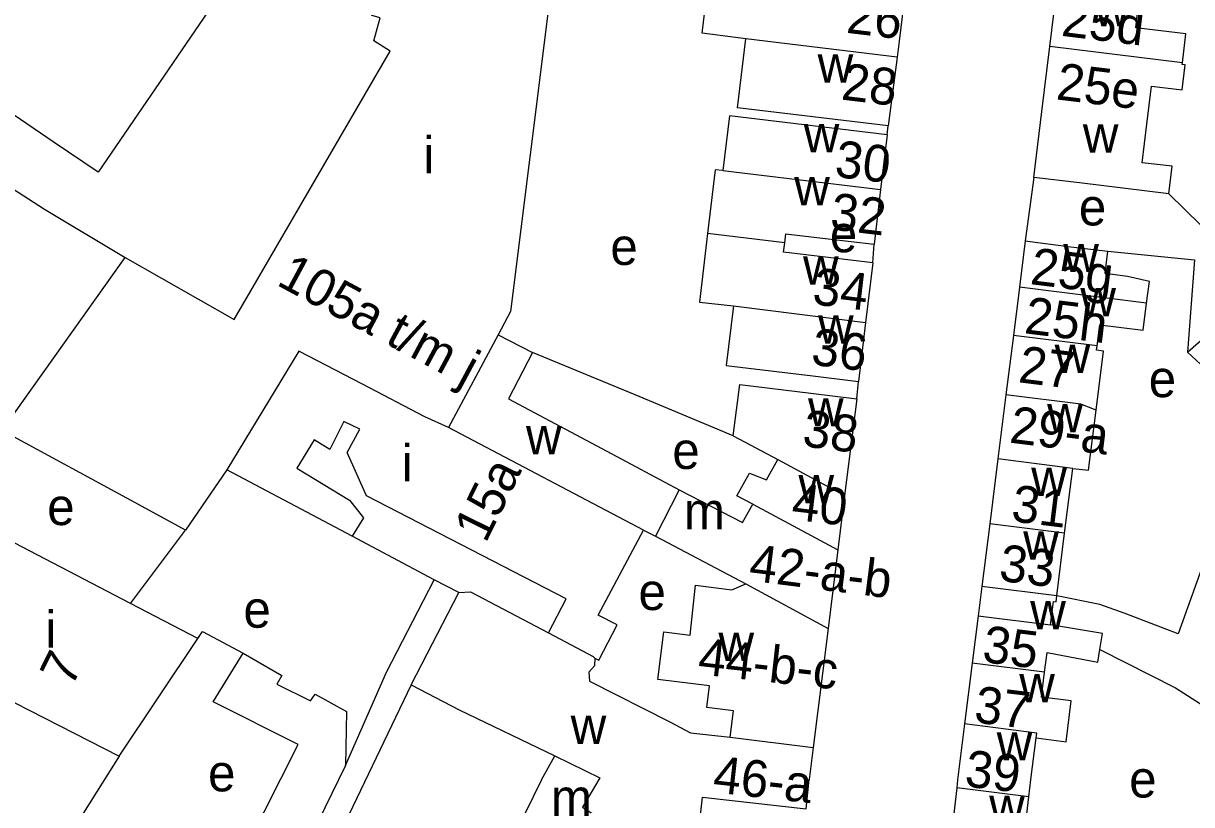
# Model space of a CAD drawing. Extents: x 159700 to 161346, y 381730 to 382922.
# Drawn here: x 160801.9 to 160928.7, y 382497.3 to 382582.1 of the extents above; entities that cross this region are included whole.
import ezdxf

# ---------------------------------------------------------------- set-up
doc = ezdxf.new("R2010")
doc.units = 0
for name, color, linetype in [('BLT_Basislijn', 7, 'Continuous'), ('BLT_Bebouwing', 7, 'Continuous'), ('BLT_Centroide', 7, 'Continuous'), ('BLT_Huisnummer', 7, 'Continuous'), ('BLT_Huisnummer_ tussenligend', 7, 'Continuous'), ('BLT_Huisnummer_reeks', 7, 'Continuous'), ('BLT_Onderdoorgang_en_onderverdeling', 7, 'Continuous'), ('BLT_Onderverdeling_panden', 7, 'Continuous')]:
    doc.layers.add(name, color=color, linetype=linetype)

msp = doc.modelspace()

# ---------------------------------------------------------------- linework, layer by layer
at = {"layer": 'BLT_Basislijn'}
for p, q in [((160895.67, 382570.01), (160895.79, 382570.98)), ((160797.58, 382566.19), (160804.24, 382561.93)), ((160911.6, 382565.37), (160910.65, 382558.47)), ((160804.24, 382561.93), (160813, 382556.68)), ((160894.11, 382556.11), (160894.25, 382558.11)), ((160868.34, 382541.79), (160857.19, 382546.37)), ((160892.39, 382541.35), (160892.57, 382543.22)), ((160878.98, 382537.32), (160868.34, 382541.79)), ((160813.56, 382519.14), (160819.53, 382527.09)), ((160846.52, 382521.7), (160837.63, 382526.42)), ((160841.34, 382511.67), (160846.52, 382521.7)), ((160849.19, 382520.32), (160846.52, 382521.7)), ((160836.89, 382501.55), (160841.34, 382511.67)), ((160844.01, 382510.3), (160831.41, 382483.99)), ((160812.33, 382502.56), (160805.67, 382492.01))]:
    msp.add_line(p, q, dxfattribs=at)
for points in [[(160951.83, 382567.37), (160949.25, 382570.37), (160948.92, 382570.37), (160946.35, 382568.47), (160933.21, 382556.75), (160926.24, 382563.59)], [(160919.62, 382557.35), (160929.02, 382556.44), (160928.26, 382546.4)], [(160934.87, 382533.23), (160932.92, 382532.91), (160931.78, 382529.63), (160932.15, 382529.42), (160927.26, 382515.85), (160921.38, 382518.08)], [(160921.38, 382518.08), (160918.77, 382519.01), (160914.08, 382519.95)], [(160820.88, 382515.32), (160821.39, 382516.08), (160825.78, 382513.72)], [(160918.77, 382514.15), (160926.98, 382509.98), (160933.19, 382505.98), (160932.52, 382501.95)]]:
    msp.add_lwpolyline(points, dxfattribs=at)
at = {"layer": 'BLT_Bebouwing'}
for p, q in [((160860.97, 382600.04), (160854.79, 382550.82)), ((160913.33, 382579.57), (160914.11, 382585.95)), ((160912.47, 382572.52), (160913.33, 382579.57)), ((160896.76, 382578.41), (160895.79, 382570.98)), ((160911.6, 382565.37), (160912.47, 382572.52)), ((160895.67, 382570.01), (160894.96, 382564.07)), ((160894.96, 382564.07), (160894.25, 382558.11)), ((160910.65, 382558.47), (160910.03, 382553.46)), ((160928.26, 382546.4), (160940.68, 382557.44)), ((160894.11, 382556.11), (160893.34, 382549.63)), ((160910.03, 382553.46), (160909.37, 382548.22)), ((160854.79, 382550.82), (160853.45, 382548.3)), ((160893.34, 382549.63), (160892.57, 382543.22)), ((160853.45, 382548.3), (160857.19, 382546.37)), ((160909.37, 382548.22), (160908.56, 382541.77)), ((160857.19, 382546.37), (160854.59, 382541.34)), ((160936.84, 382538.5), (160928.26, 382546.4)), ((160854.59, 382541.34), (160865.24, 382535.67)), ((160892.39, 382541.35), (160891.04, 382530.84)), ((160908.56, 382541.77), (160907.69, 382534.81)), ((160878.98, 382537.32), (160883.83, 382534.74)), ((160865.24, 382535.67), (160873.12, 382531.47)), ((160907.69, 382534.81), (160906.81, 382527.79)), ((160824.03, 382533.65), (160819.53, 382527.09)), ((160837.63, 382526.42), (160824.03, 382533.65)), ((160914.93, 382526.77), (160915.81, 382533.79)), ((160873.12, 382531.47), (160879.98, 382527.92)), ((160891.04, 382530.84), (160890.34, 382524.96)), ((160819.53, 382527.09), (160814.42, 382529.87)), ((160879.98, 382527.92), (160881.1, 382529.9)), ((160869.25, 382527.1), (160870.52, 382526.43)), ((160906.81, 382527.79), (160905.95, 382520.97)), ((160870.52, 382526.43), (160880.33, 382521.26)), ((160890.34, 382524.96), (160889.27, 382516.43)), ((160905.95, 382520.97), (160905.55, 382517.79)), ((160905.55, 382517.79), (160904.91, 382512.65)), ((160889.27, 382516.43), (160888.66, 382511.52)), ((160888.66, 382511.52), (160887.66, 382503.5)), ((160904.91, 382512.65), (160904.08, 382506.05)), ((160904.08, 382506.05), (160903.32, 382500)), ((160911.28, 382500.02), (160911.85, 382504.53)), ((160858.17, 382500), (160859.63, 382502.61)), ((160887.66, 382503.5), (160887.22, 382500.01)), ((160858.17, 382500), (160854.89, 382493.28)), ((160886.88, 382496.85), (160887.22, 382500.01)), ((160903.32, 382500), (160903.22, 382499.11)), ((160911.05, 382498.13), (160911.28, 382500.02)), ((160903.22, 382499.11), (160902.35, 382491.51)), ((160910.19, 382490.61), (160911.05, 382498.13))]:
    msp.add_line(p, q, dxfattribs=at)
for points in [[(160841.73, 382579.06), (160839.99, 382580.2), (160840.67, 382582.69), (160839.76, 382582.95), (160849.45, 382602.5), (160857.43, 382600.35), (160860.02, 382604.55)], [(160835.82, 382601.89), (160833.5, 382598.49), (160833.58, 382598.43), (160831.95, 382596.05), (160831.04, 382596.67), (160810.06, 382565.93), (160805.18, 382569.24), (160794.52, 382576.51)], [(160880.34, 382580.41), (160875.6, 382581.03), (160876.05, 382584.63), (160885.71, 382583.41), (160886.18, 382587.2)], [(160897.67, 382585.83), (160896.99, 382580.17), (160896.76, 382578.41)], [(160927.71, 382577.82), (160928.09, 382580.94), (160922.65, 382581.61), (160923.04, 382584.86)], [(160895.79, 382570.98), (160879.45, 382572.93), (160880.34, 382580.41)], [(160813, 382556.68), (160824.82, 382549.96), (160841.73, 382579.06)], [(160923.86, 382571.15), (160924.36, 382575.29), (160927.69, 382574.88), (160928.02, 382577.6), (160927.69, 382577.64), (160927.71, 382577.82)], [(160895.67, 382570.01), (160878.55, 382572.06), (160877.84, 382566.11)], [(160926.24, 382563.59), (160926.61, 382566.58), (160923.35, 382566.97), (160923.86, 382571.15)], [(160877.84, 382566.11), (160877.02, 382566.21), (160876.19, 382559.27)], [(160926.24, 382563.59), (160916.56, 382564.77), (160911.6, 382565.37)], [(160876.19, 382559.27), (160875.3, 382551.82), (160878.99, 382551.44)], [(160884.56, 382558.27), (160884.68, 382559.26), (160889.29, 382558.71), (160894.25, 382558.11)], [(160910.65, 382558.47), (160915.62, 382557.85), (160919.62, 382557.35)], [(160894.11, 382556.11), (160884.44, 382557.27), (160884.56, 382558.27)], [(160923.83, 382551.73), (160924.13, 382554.09), (160921.75, 382554.62), (160919.32, 382554.93), (160919.62, 382557.35)], [(160799.64, 382537.89), (160813, 382556.68)], [(160878.99, 382551.44), (160878.2, 382544.94), (160887.6, 382543.82), (160892.57, 382543.22)], [(160918.45, 382547.08), (160918.74, 382549.38), (160923.46, 382548.78), (160923.83, 382551.73)], [(160918.34, 382540.12), (160919.15, 382546.53), (160918.39, 382546.62), (160918.45, 382547.08)], [(160878.98, 382537.32), (160879.68, 382542.88), (160887.38, 382541.96), (160892.39, 382541.35)], [(160915.81, 382533.79), (160917.52, 382533.58), (160918.34, 382540.12)], [(160858.93, 382515.93), (160860.86, 382519.63), (160839.16, 382530.8), (160837.07, 382535.5), (160838.44, 382538.05), (160836.73, 382538.89), (160835.2, 382535.85), (160833.49, 382536.88), (160831.62, 382533.8), (160837.32, 382530.35), (160838.85, 382528.42), (160837.63, 382526.42)], [(160814.42, 382529.87), (160799.64, 382537.89)], [(160881.1, 382529.9), (160879.36, 382530.83), (160880.75, 382533.29), (160882.59, 382532.55), (160883.83, 382534.74)], [(160813.56, 382519.14), (160798.42, 382527.03), (160799.16, 382528.46)], [(160863.94, 382513.21), (160864.39, 382512.97), (160866.37, 382516.8), (160864.32, 382517.85), (160869.25, 382527.1)], [(160914.08, 382519.95), (160914.93, 382526.77)], [(160795.05, 382520.98), (160791.22, 382513.34), (160812.33, 382502.56)], [(160844.01, 382510.3), (160849.19, 382520.32)], [(160849.19, 382520.32), (160850.45, 382520.39), (160858.93, 382515.93)], [(160878.65, 382504.63), (160879.01, 382507.46), (160876.1, 382507.83), (160876.4, 382510.18), (160870.79, 382510.89), (160871.44, 382516.04), (160874.29, 382515.68), (160874.88, 382521.11), (160878.83, 382520.61), (160880.33, 382521.26)], [(160820.88, 382515.32), (160813.56, 382519.14)], [(160913.4, 382516.82), (160913.71, 382519.35), (160914, 382519.31), (160914.08, 382519.95)], [(160918.77, 382514.15), (160919.06, 382515.87), (160913.4, 382516.82)], [(160812.33, 382502.56), (160820.88, 382515.32)], [(160912.74, 382511.67), (160913.03, 382513.82), (160918.54, 382512.75), (160918.77, 382514.15)], [(160824.37, 382489.21), (160831.76, 382503.82), (160822.54, 382508.46), (160825.78, 382513.72)], [(160825.78, 382513.72), (160830, 382511.33), (160829.45, 382510.38), (160833.1, 382508.56), (160833.61, 382509.3), (160837, 382507.39)], [(160863.94, 382513.21), (160863.91, 382512.36), (160863.3, 382511.66), (160863.37, 382510.71), (160872.1, 382506.28), (160874.32, 382505.08), (160878.65, 382504.63)], [(160911.85, 382504.53), (160915.11, 382504.13), (160915.65, 382508.56), (160912.43, 382508.96), (160912.74, 382511.67)], [(160844.01, 382510.3), (160849.22, 382507.57), (160859.63, 382502.61)], [(160837, 382507.39), (160836.89, 382501.55)], [(160836.89, 382501.55), (160823.53, 382474.14)]]:
    msp.add_lwpolyline(points, dxfattribs=at)
at = {"layer": 'BLT_Onderdoorgang_en_onderverdeling'}
for p, q in [((160914.08, 382519.95), (160905.95, 382520.97)), ((160905.55, 382517.79), (160913.4, 382516.82))]:
    msp.add_line(p, q, dxfattribs=at)
at = {"layer": 'BLT_Onderverdeling_panden'}
for p, q in [((160896.76, 382578.41), (160880.34, 382580.41)), ((160927.71, 382577.82), (160913.33, 382579.57)), ((160884.56, 382558.27), (160876.19, 382559.27)), ((160923.83, 382551.73), (160910.03, 382553.46)), ((160878.99, 382551.44), (160893.34, 382549.63)), ((160853.45, 382548.3), (160848.09, 382538.24)), ((160918.45, 382547.08), (160909.37, 382548.22)), ((160869.25, 382527.1), (160848.09, 382538.24)), ((160883.83, 382534.74), (160891.04, 382530.84)), ((160915.81, 382533.79), (160907.69, 382534.81)), ((160873.12, 382531.47), (160870.52, 382526.43)), ((160881.1, 382529.9), (160890.34, 382524.96)), ((160914.93, 382526.77), (160906.81, 382527.79)), ((160880.33, 382521.26), (160889.27, 382516.43)), ((160858.93, 382515.93), (160863.78, 382513.37)), ((160863.78, 382513.37), (160863.94, 382513.21)), ((160912.74, 382511.67), (160904.91, 382512.65)), ((160911.05, 382498.13), (160903.22, 382499.11))]:
    msp.add_line(p, q, dxfattribs=at)
for points in [[(160877.84, 382566.11), (160894.96, 382564.07)], [(160838.74, 382542.92), (160831.83, 382546.51), (160824.03, 382533.65)], [(160848.09, 382538.24), (160845.52, 382539.4), (160838.74, 382542.92)], [(160918.34, 382540.12), (160916.69, 382540.75), (160908.56, 382541.77)], [(160911.85, 382504.53), (160911.92, 382505.07), (160904.08, 382506.05)], [(160878.65, 382504.63), (160887.66, 382503.5)], [(160859.63, 382502.61), (160864.48, 382500.21), (160862.62, 382497.04), (160864.15, 382496.03), (160875.29, 382494.8), (160875.65, 382498.11), (160886.88, 382496.85)]]:
    msp.add_lwpolyline(points, dxfattribs=at)

# ---------------------------------------------------------------- texts
at = {"layer": 'BLT_Centroide'}
for s, p in [('w', (160918.13, 382581.78)), ('w', (160888.13, 382575.66)), ('w', (160886.62, 382568.09)), ('w', (160916.91, 382568.06)), ('i', (160845.35, 382565.81)), ('w', (160885.59, 382562.34)), ('e', (160916.48, 382560.16)), ('e', (160889.46, 382557.25)), ('e', (160865.64, 382555.87)), ('w', (160914.79, 382555.09)), ('w', (160886.55, 382553.72)), ('w', (160916.64, 382550.28)), ('w', (160888.18, 382547.34)), ('w', (160913.85, 382544.16)), ('e', (160924.06, 382541.52)), ('w', (160887.09, 382538.34)), ('w', (160913.04, 382537.69)), ('w', (160856.48, 382535.32)), ('e', (160872.36, 382533.73)), ('i', (160842.99, 382532.38)), ('w', (160886.05, 382530)), ('w', (160911.31, 382530.78)), ('e', (160804.53, 382527.64)), ('m', (160873.62, 382527.18)), ('w', (160910.44, 382523.88)), ('e', (160868.69, 382518.42)), ('e', (160825.82, 382516.5)), ('w', (160911.2, 382516.31)), ('i', (160804.33, 382514.32)), ('w', (160877.37, 382512.88)), ('w', (160910.01, 382508.41)), ('w', (160861.33, 382503.87)), ('w', (160907.56, 382502.09)), ('e', (160821.98, 382498.74)), ('e', (160921.94, 382498.07)), ('m', (160859.19, 382496.07)), ('w', (160906.75, 382495.19))]:
    msp.add_text(s, height=4, dxfattribs=at).set_placement(p)
at = {"layer": 'BLT_Huisnummer'}
for s, rotation, p in [('28', 353.1678, (160890.6, 382573.83)), ('25e', 353.0512, (160913.92, 382573.85)), ('32', 353.165, (160889.38, 382559.76)), ('25g', 352.9358, (160911.1, 382553.8)), ('25h', 352.9375, (160910.46, 382548.47)), ('36', 352.7954, (160887.32, 382545.07)), ('27', 352.9375, (160909.82, 382543.15)), ('15a', 63.645, (160852.1, 382525.58)), ('40', 353.165, (160885.19, 382528.26)), ('31', 352.938, (160909.04, 382528.07)), ('35', 352.938, (160905.9, 382512.79)), ('7', 63.7717, (160807.17, 382509.93)), ('39', 353.5586, (160903.99, 382499.28))]:
    msp.add_text(s, height=4, rotation=rotation, dxfattribs=at).set_placement(p)
at = {"layer": 'BLT_Huisnummer_ tussenligend'}
for s, rotation, p in [('26', 353.1725, (160891.15, 382581.08)), ('25d', 353.0458, (160914.48, 382580.75)), ('30', 353.1678, (160889.88, 382565.45)), ('34', 353.165, (160887.46, 382551.62)), ('38', 352.7954, (160886.37, 382536.21)), ('33', 352.938, (160907.71, 382521.61)), ('37', 352.938, (160905.01, 382506.24))]:
    msp.add_text(s, height=4, rotation=rotation, dxfattribs=at).set_placement(p)
at = {"layer": 'BLT_Huisnummer_reeks'}
for s, rotation, p in [('105a t/m j', 331.7614, (160829.29, 382553.76)), ('29-a', 352.9375, (160908.85, 382536.6)), ('42-a-b', 352.7809, (160880.57, 382521.63)), ('44-b-c', 353.6755, (160875.04, 382511.46)), ('46-a', 353.6664, (160876.67, 382498.64))]:
    msp.add_text(s, height=4, rotation=rotation, dxfattribs=at).set_placement(p)

doc.saveas('drawing.dxf')
